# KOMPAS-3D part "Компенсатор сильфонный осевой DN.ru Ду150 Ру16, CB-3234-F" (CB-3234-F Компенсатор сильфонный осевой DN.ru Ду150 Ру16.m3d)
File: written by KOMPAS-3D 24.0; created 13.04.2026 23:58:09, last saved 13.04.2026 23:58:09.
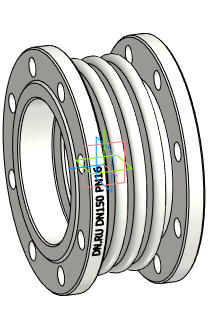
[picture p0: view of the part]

Document properties: Автор: DN.RU; Полное имя файла: D:\PROJECT CAD\DN.RU\...198(ACTUALE). CB-3234-F Компенсатор сильфонный осевой DN.ru\Исходники\DN150\CB-3234-F Компенсатор сильфонный осевой DN.ru Ду150 Ру16.m3d

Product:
- Body: Твердое тело1  | qty 1
    Масса: 16.970428
- Part/product: Компенсатор сильфонный осевой DN.ru Ду150 Ру16  | designation CB-3234-F
    Масса: 12.5
    Раздел спецификации: Прочие изделия
    Комментарий: D140-02118
    Примечание: D140-02118
    additional columns: Типовые

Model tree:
1. Твердое тело1  (labels: Твердое тело1)

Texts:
  CB-3234-F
